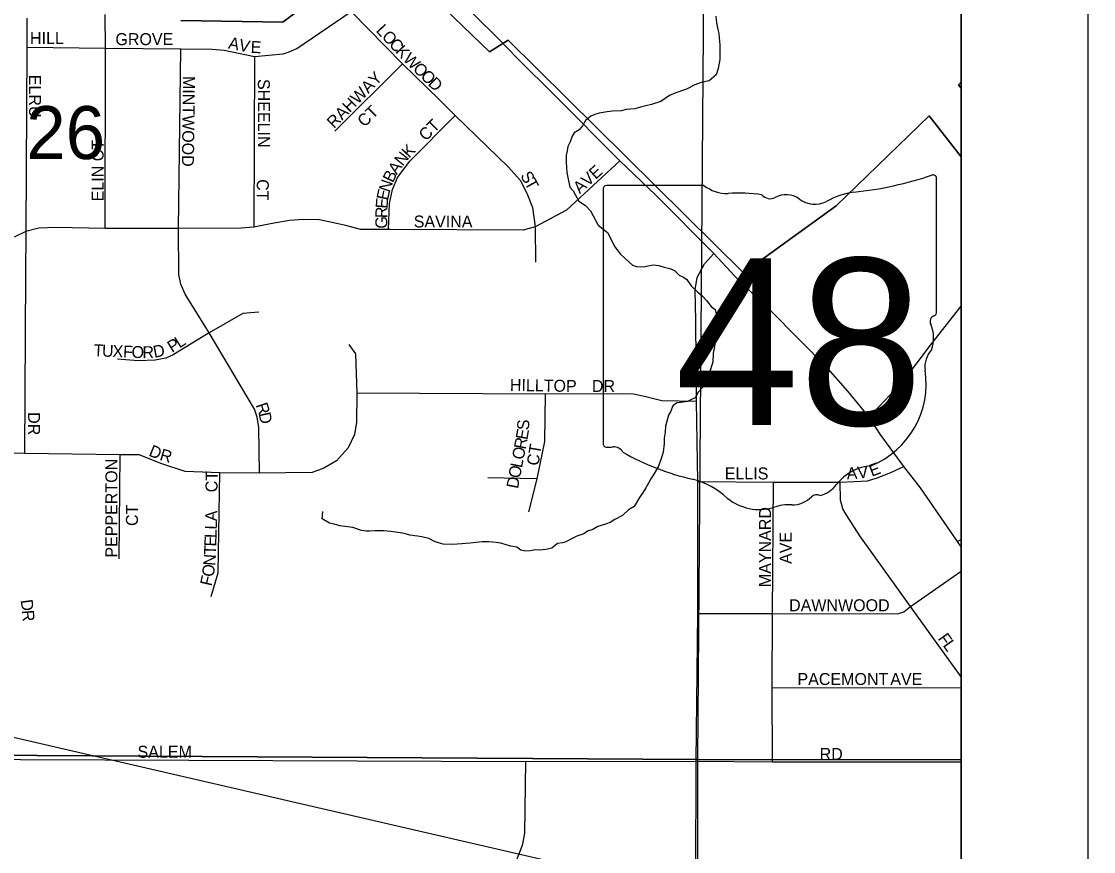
# Model space of a CAD drawing. Extents: x -209 to 4852, y 0 to 905.
# Drawn here: x 375.98 to 392.92, y 256.85 to 269.97 of the extents above; entities that cross this region are included whole.
import ezdxf

# ---------------------------------------------------------------- set-up
doc = ezdxf.new("R2010")
doc.units = 0
for name, color, linetype in [('Default', 7, 'Continuous'), ('GM_X_Airport_Location_Class_2', 7, 'Continuous'), ('GM_X_Airport_Location_Class_3', 7, 'Continuous'), ('GM_X_County_Road', 7, 'Continuous'), ('GM_X_County_Subdivision_Text', 7, 'Continuous'), ('GM_X_Minor_River', 7, 'Continuous'), ('GM_X_Township_Road_Text', 7, 'Continuous'), ('GM_X_Township_ROW', 7, 'Continuous'), ('GM_X_Township_Subdivision', 7, 'Continuous'), ('GM_X_US_Location', 7, 'Continuous'), ('SH_Data', 7, 'Continuous'), ('SH_Text', 7, 'Continuous')]:
    doc.layers.add(name, color=color, linetype=linetype)

msp = doc.modelspace()

# ---------------------------------------------------------------- linework, layer by layer
at = {"layer": 'Default'}
msp.add_lwpolyline([(390.832, 338.559), (254.832, 338.559), (254.832, 202.559), (390.832, 202.559)], close=True, dxfattribs=at)
at = {"layer": 'GM_X_Airport_Location_Class_2'}
msp.add_line((390.775, 261.751), (390.832, 261.784), dxfattribs=at)
for points in [[(376.058, 269.566), (377.306, 269.552), (378.494, 269.542), (378.988, 269.535), (379.179, 269.522), (379.661, 269.42), (380.115, 269.461), (380.21, 269.493), (380.327, 269.548), (381.186, 270.131), (382.291, 270.908)], [(376.058, 270.024), (376.058, 269.566), (376.043, 266.655), (376.039, 265.976)], [(377.3, 266.702), (377.306, 269.552), (377.3, 270.086)], [(381.186, 270.131), (382.001, 269.307), (382.577, 268.74)], [(379.739, 262.835), (379.73, 263.554), (379.704, 263.716), (379.662, 263.844), (378.943, 265.051), (378.566, 265.663), (378.497, 265.819), (378.464, 265.975), (378.457, 266.699), (378.494, 269.542)], [(379.661, 269.42), (379.649, 266.722)], [(380.928, 268.239), (382.001, 269.307)], [(382.577, 268.74), (382.832, 268.489), (383.677, 267.671), (383.86, 267.466), (383.964, 267.26), (384.053, 267.032), (384.099, 266.725), (384.103, 266.17)], [(381.776, 266.685), (381.792, 267.096), (381.842, 267.317), (381.923, 267.507), (382.116, 267.765), (382.832, 268.489)], [(385.433, 267.773), (384.594, 266.991), (384.099, 266.725), (383.907, 266.674), (381.811, 266.685)], [(381.811, 266.685), (381.776, 266.685), (381.337, 266.685), (381.106, 266.749), (380.686, 266.837), (380.436, 266.845), (380.215, 266.829), (379.914, 266.774), (379.649, 266.722), (379.454, 266.705), (378.457, 266.699), (377.3, 266.702), (376.519, 266.719), (376.25, 266.705), (376.043, 266.655), (375.872, 266.572), (375.367, 266.544)], [(386.629, 254.612), (386.643, 258.282), (386.67, 260.614), (386.666, 262.704), (386.649, 263.966), (386.635, 265.244), (386.624, 265.732), (386.657, 265.925), (386.776, 266.144), (386.924, 266.304)], [(376.039, 265.976), (376.024, 263.142)], [(389.377, 263.718), (389.941, 264.321), (390.345, 264.858), (390.832, 265.472)], [(379.727, 265.378), (379.475, 265.358), (378.943, 265.051)], [(378.943, 265.051), (378.373, 264.705), (378.26, 264.652), (378.089, 264.62), (377.822, 264.608), (377.495, 264.638)], [(381.152, 264.869), (381.255, 264.72), (381.279, 264.098), (381.273, 263.64), (381.243, 263.442), (381.143, 263.236), (380.958, 263.03), (380.758, 262.911), (380.57, 262.845), (379.739, 262.835), (379.11, 262.836), (378.564, 262.861), (378.197, 262.981), (377.834, 263.125), (377.535, 263.125), (376.024, 263.142), (375.742, 263.148)], [(386.649, 263.966), (386.097, 263.976), (385.849, 264.038), (385.653, 264.08), (385.481, 264.087), (384.254, 264.082), (381.279, 264.098)], [(384.254, 264.082), (384.247, 263.335), (384.123, 262.743), (383.994, 262.222)], [(377.52, 261.481), (377.535, 263.125)], [(386.666, 262.704), (387.863, 262.692), (388.916, 262.69), (389.349, 262.713), (389.505, 262.757), (389.719, 262.842), (389.924, 262.937)], [(378.974, 260.881), (379.084, 261.26), (379.11, 262.836)], [(384.123, 262.743), (383.348, 262.758)], [(387.847, 258.268), (387.842, 259.441), (387.849, 260.614), (387.863, 262.692)], [(390.832, 259.611), (390.033, 260.724), (389.227, 261.844), (389.011, 262.18), (388.959, 262.269), (388.926, 262.406), (388.916, 262.69)], [(386.67, 260.614), (387.849, 260.614), (389.827, 260.611), (389.927, 260.64), (390.033, 260.724), (390.832, 261.286)], [(387.842, 259.441), (389.423, 259.446), (390.832, 259.442)], [(368.676, 258.342), (375.958, 258.306), (383.945, 258.276), (386.643, 258.282), (387.847, 258.268), (390.832, 258.269)], [(383.945, 258.276), (383.927, 257.141), (383.89, 256.949), (383.736, 256.556), (383.453, 256.136), (383.292, 256.048), (383.133, 256.005), (382.936, 255.998), (382.109, 256.02), (381.995, 255.99), (381.878, 255.916), (381.758, 255.796), (381.698, 255.637), (381.664, 253.92), (381.626, 252.277), (381.644, 252.128), (381.723, 251.754), (381.706, 249.988), (381.716, 249.794), (381.773, 249.483)]]:
    msp.add_lwpolyline(points, dxfattribs=at)
at = {"layer": 'GM_X_County_Road'}
for points in [[(386.951, 270.06), (386.964, 269.954), (386.985, 269.847), (386.999, 269.786), (387.012, 269.656), (387.018, 269.603), (387.014, 269.375), (386.989, 269.231), (386.956, 269.133), (386.848, 269.036), (386.719, 269.008), (386.619, 268.971), (386.489, 268.905), (386.321, 268.848), (386.222, 268.804), (386.083, 268.707), (385.938, 268.664), (385.847, 268.643), (385.763, 268.622), (385.671, 268.593), (385.534, 268.58), (385.458, 268.559), (385.321, 268.554), (385.237, 268.547), (385.108, 268.527), (385.039, 268.505), (384.978, 268.476), (384.893, 268.409), (384.846, 268.326), (384.792, 268.259), (384.715, 268.215), (384.684, 268.162), (384.652, 268.071), (384.612, 267.996), (384.604, 267.928), (384.587, 267.86), (384.585, 267.753), (384.591, 267.662), (384.597, 267.586), (384.611, 267.509), (384.646, 267.357), (384.698, 267.295), (384.786, 267.134), (384.891, 267.064), (384.973, 266.978), (385.091, 266.756), (385.24, 266.639), (385.358, 266.409), (385.447, 266.293), (385.581, 266.169), (385.633, 266.123), (385.701, 266.099), (385.815, 266.097), (385.876, 266.111), (385.967, 266.125), (386.051, 266.116), (386.134, 266.091), (386.224, 266.067), (386.3, 266.035), (386.374, 265.965), (386.442, 265.934), (386.494, 265.895), (386.561, 265.795), (386.665, 265.702), (386.74, 265.632), (386.807, 265.562), (386.881, 265.47), (386.941, 265.423), (386.962, 265.332), (386.969, 265.263), (386.966, 265.103), (386.957, 265.05), (386.94, 264.937), (386.93, 264.83), (386.913, 264.732), (386.903, 264.588), (386.887, 264.527), (386.854, 264.421), (386.838, 264.345), (386.791, 264.278), (386.759, 264.202), (386.674, 264.113), (386.627, 264.022), (386.558, 263.993)], [(386.558, 263.993), (386.504, 263.964), (386.398, 263.95), (386.337, 263.944), (386.275, 263.899), (386.236, 263.801), (386.204, 263.748), (386.156, 263.575), (386.154, 263.483), (386.137, 263.385), (386.135, 263.301), (386.118, 263.165), (386.102, 263.112), (386.085, 263.051), (386.045, 262.945), (385.975, 262.817), (385.928, 262.742), (385.889, 262.675), (385.849, 262.599), (385.802, 262.532), (385.748, 262.449), (385.662, 262.306), (385.57, 262.254), (385.477, 262.165), (385.354, 262.099), (385.285, 262.054), (385.224, 262.033), (385.14, 262.004), (385.086, 261.989), (385.01, 261.945), (384.926, 261.916), (384.864, 261.872), (384.757, 261.836), (384.68, 261.799), (384.581, 261.747), (384.527, 261.733), (384.451, 261.719), (384.359, 261.645), (384.267, 261.624), (384.169, 261.618), (384.1, 261.619), (384.016, 261.605), (383.948, 261.599), (383.872, 261.616), (383.805, 261.662), (383.714, 261.679), (383.654, 261.695), (383.556, 261.728), (383.48, 261.737), (383.366, 261.746), (383.26, 261.748), (383.07, 261.729), (382.94, 261.716), (382.788, 261.703), (382.644, 261.713), (382.569, 261.73), (382.508, 261.754), (382.418, 261.801), (382.305, 261.826), (382.237, 261.835), (382.115, 261.852), (382.063, 261.868), (382.002, 261.884), (381.889, 261.902), (381.813, 261.911), (381.699, 261.92), (381.57, 261.922), (381.479, 261.917), (381.418, 261.918), (381.35, 261.926), (381.214, 261.974), (381.093, 261.992), (381.01, 262.001), (380.919, 262.025), (380.843, 262.042), (380.731, 262.112), (380.741, 262.226)]]:
    msp.add_lwpolyline(points, dxfattribs=at)
at = {"layer": 'GM_X_County_Subdivision_Text'}
for points in [[(383.528, 269.688), (383.521, 269.695), (383.125, 270.086), (383.116, 270.095)], [(390.832, 261.669), (390.775, 261.751), (390.191, 262.6), (389.924, 262.937), (389.553, 263.451), (389.377, 263.718), (389.038, 264.13), (388.728, 264.48), (387.809, 265.417), (387.317, 265.879), (386.924, 266.304), (386.007, 267.229), (385.433, 267.773), (384.418, 268.791), (383.814, 269.396), (383.528, 269.688)]]:
    msp.add_lwpolyline(points, dxfattribs=at)
at = {"layer": 'GM_X_Minor_River'}
for points in [[(366.685, 278.54), (386.82, 278.559), (386.662, 258.306), (366.643, 258.429)], [(390.832, 258.301), (390.832, 278.515), (386.82, 278.559), (386.662, 258.306)], [(386.662, 258.306), (386.645, 238.294), (385.487, 238.317), (366.505, 238.365), (366.643, 258.429)], [(390.832, 238.271), (390.832, 258.301), (386.662, 258.306), (386.645, 238.294)]]:
    msp.add_lwpolyline(points, close=True, dxfattribs=at)
at = {"layer": 'GM_X_Township_Subdivision'}
for p, q in [((390.444, 265.388), (390.444, 267.481)), ((385.17, 267.313), (385.17, 263.311)), ((386.767, 267.382), (385.222, 267.382)), ((390.443, 265.388), (390.444, 265.388))]:
    msp.add_line(p, q, dxfattribs=at)
for centre, radius, start, end in [((388.565, 272.839), 5.592, 275.8445, 288.9065), ((390.385, 267.49), 0.0587, 351.8621, 97.738), ((385.231, 267.322), 0.0611, 98.1301, 188.1301), ((387.134, 267.847), 0.593, 231.6195, 271.1119), ((387.331, 265.135), 2.127, 80.4867, 94.9883), ((387.814, 267.343), 0.171, 219.7921, 297.1024), ((388.065, 266.88), 0.355, 54.4667, 119.1411), ((388.524, 267.514), 0.428, 233.8562, 294.8282), ((389.279, 266.16), 1.125, 97.3462, 120.7689), ((390.43, 265.234), 0.0909, 107.944, 210.337), ((390.381, 265.38), 0.0628, 289.6038, 7.7341), ((389.852, 264.969), 0.545, 340.033, 23.6496), ((390.654, 264.511), 0.397, 136.8065, 186.9296), ((388.879, 264.245), 1.399, 292.3089, 8.9858), ((385.231, 263.302), 0.0616, 171.9584, 258.3066), ((385.241, 263.712), 0.47, 267.339, 280.6039), ((385.337, 263.08), 0.17, 29.7484, 93.2717), ((387.478, 266.676), 4.038, 240.4129, 257.1985), ((389.468, 262.187), 0.766, 94.4031, 142.5768), ((386.274, 261.513), 1.264, 47.1842, 75.836), ((388.498, 262.923), 0.452, 282.8732, 323.2771), ((387.641, 263.06), 0.802, 230.7004, 286.2918), ((388.163, 262.76), 0.427, 268.777, 315.5493), ((388.549, 262.373), 0.12, 65.7517, 132.6484), ((388.104, 261.676), 0.659, 85.6951, 111.2099)]:
    msp.add_arc(centre, radius, start, end, dxfattribs=at)
at = {"layer": 'GM_X_US_Location'}
for points in [[(378.495, 269.99), (380.106, 269.962), (381.675, 271.136), (383.375, 269.495), (383.67, 269.68), (387.393, 265.999), (388.856, 267.062), (390.327, 268.483), (390.832, 267.836), (390.832, 268.918), (390.79, 268.974), (390.832, 269.015), (390.832, 278.706)], [(286.607, 238.38), (390.832, 238.067), (390.832, 267.836), (390.327, 268.483), (388.856, 267.062), (387.393, 265.999), (383.67, 269.68), (383.375, 269.495), (381.675, 271.136), (380.106, 269.962), (378.495, 269.99)], [(286.607, 238.38), (390.832, 238.067), (390.832, 267.836), (390.327, 268.483), (388.856, 267.062), (387.393, 265.999), (383.67, 269.68), (383.375, 269.495), (381.675, 271.136), (380.106, 269.962), (378.495, 269.99)]]:
    msp.add_lwpolyline(points, dxfattribs=at)
msp.add_lwpolyline([(390.832, 269.015), (390.79, 268.974), (390.832, 268.918)], close=True, dxfattribs=at)
msp.add_lwpolyline([(390.832, 269.015), (390.79, 268.974), (390.832, 268.918)], close=True, dxfattribs=at)
at = {"layer": 'SH_Data'}
for p, q in [((392.832, 340.559), (392.832, 200.559)), ((390.832, 338.559), (390.832, 202.559))]:
    msp.add_line(p, q, dxfattribs=at)
at = {"layer": 'SH_Text'}
msp.add_lwpolyline([(329.283, 269.416), (400.488, 252.966), (430.167, 252.966), (430.167, 247.327), (400.495, 247.1)], close=True, dxfattribs=at)

# ---------------------------------------------------------------- texts
at = {"layer": 'GM_X_Airport_Location_Class_3'}
for s, height, rotation, p in [('L', 0.189, 312.9905, (381.57, 269.822)), ('HILL', 0.1894, 0, (376.111, 269.617)), ('GROVE', 0.1894, 0, (377.461, 269.6)), ('A', 0.189, 348.4243, (379.236, 269.549)), ('V', 0.189, 348.4029, (379.4, 269.516)), ('E', 0.189, 357.5296, (379.596, 269.478)), ('O', 0.189, 312.975, (381.661, 269.725)), ('C', 0.189, 312.9887, (381.775, 269.603)), ('K', 0.189, 313.1362, (381.877, 269.493)), ('W', 0.189, 315.2047, (381.996, 269.366)), ('RAHWAY', 0.1894, 45.6582, (380.918, 268.273)), ('O', 0.189, 315.955, (382.152, 269.211)), ('O', 0.189, 315.9427, (382.272, 269.095)), ('ELRU', 0.1894, 270, (376.096, 269.131)), ('MINTWOOD', 0.1894, 269.2724, (378.53, 269.114)), ('SHEELIN', 0.1894, 270, (379.713, 269.065)), ('D', 0.189, 315.9427, (382.392, 268.979)), ('CT', 0.1894, 45, (381.399, 268.293)), ('CT', 0.1894, 45, (382.369, 268.073)), ('ELIN CT', 0.1894, 90, (377.275, 267.131)), ('K', 0.189, 45.9584, (382.103, 267.803)), ('N', 0.189, 51.5825, (382.002, 267.677)), ('B', 0.189, 64.1191, (381.847, 267.414)), ('A', 0.189, 54.9704, (381.909, 267.542)), ('AVE', 0.1894, 42.2752, (384.803, 267.241)), ('CT', 0.1894, 270, (379.696, 267.481)), ('N', 0.189, 71.4268, (381.796, 267.262)), ('S', 0.189, 300.7717, (383.856, 267.537)), ('T', 0.189, 298.8874, (383.923, 267.424)), ('E', 0.189, 78.0579, (381.77, 267.137)), ('E', 0.189, 85.8443, (381.762, 267.011)), ('R', 0.189, 89.3525, (381.76, 266.864)), ('G', 0.189, 89.3661, (381.758, 266.698)), ('SAVINA', 0.1894, 0, (382.177, 266.717)), ('P', 0.189, 31.3463, (378.356, 264.731)), ('L', 0.189, 32.5722, (378.473, 264.803)), ('T', 0.189, 357.4309, (377.112, 264.684)), ('U', 0.189, 357.3984, (377.246, 264.678)), ('X', 0.189, 357.4258, (377.412, 264.67)), ('F', 0.189, 357.4412, (377.579, 264.663)), ('O', 0.189, 358.1463, (377.714, 264.657)), ('R', 0.189, 0.3739, (377.889, 264.651)), ('D', 0.189, 10.741, (378.076, 264.656)), ('HILLTOP', 0.1894, 359.0307, (383.696, 264.134)), ('DR', 0.1894, 0, (384.994, 264.117)), ('R', 0.189, 288.481, (379.677, 263.912)), ('DR', 0.1894, 270, (376.08, 263.798)), ('D', 0.189, 282.2016, (379.723, 263.775)), ('S', 0.189, 87.2642, (383.999, 263.509)), ('R', 0.189, 79.1349, (383.944, 263.201)), ('E', 0.189, 80.1608, (383.973, 263.352)), ('D', 0.189, 337.6912, (377.975, 263.114)), ('R', 0.189, 343.6488, (378.149, 263.044)), ('O', 0.189, 79.1145, (383.913, 263.037)), ('CT', 0.1894, 80.5318, (384.147, 262.942)), ('PEPPERTON', 0.1894, 90, (377.492, 261.498)), ('O', 0.189, 79.1369, (383.856, 262.743)), ('L', 0.189, 79.1454, (383.888, 262.907)), ('ELLIS', 0.1894, 0, (387.094, 262.734)), ('A', 0.189, 3.6309, (389.026, 262.734)), ('V', 0.189, 6.2217, (389.202, 262.745)), ('E', 0.189, 20.7655, (389.418, 262.775)), ('CT', 0.1894, 90, (379.075, 262.531)), ('D', 0.189, 79.1145, (383.825, 262.579)), ('CT', 0.1894, 90, (377.817, 261.998)), ('A', 0.189, 88.1534, (379.068, 262.072)), ('MAYNARD', 0.1894, 90, (387.825, 261.031)), ('L', 0.189, 88.1534, (379.063, 261.939)), ('L', 0.189, 88.1534, (379.059, 261.806)), ('AVE', 0.1894, 90, (388.151, 261.398)), ('T', 0.189, 88.1534, (379.05, 261.539)), ('E', 0.189, 88.1534, (379.055, 261.672)), ('N', 0.189, 85.9721, (379.038, 261.365)), ('O', 0.189, 81.6096, (379.012, 261.185)), ('F', 0.189, 77.2471, (378.98, 261.039)), ('D', 0.189, 277.4964, (375.962, 260.825)), ('DAWNWOOD', 0.1894, 0, (388.111, 260.65)), ('R', 0.189, 274.2534, (375.983, 260.663)), ('F', 0.189, 305.5091, (390.456, 260.219)), ('L', 0.189, 305.5312, (390.534, 260.11)), ('PACEMONT', 0.1894, 0, (388.244, 259.484)), ('AVE', 0.1894, 0, (389.711, 259.484)), ('SALEM', 0.1894, 0, (377.811, 258.334)), ('RD', 0.1894, 0, (388.594, 258.3))]:
    msp.add_text(s, height=height, rotation=rotation, dxfattribs=at).set_placement(p)
at = {"layer": 'GM_X_Township_Road_Text'}
msp.add_text('26', height=0.8371, rotation=0, dxfattribs=at).set_placement((376.052, 267.799))
at = {"layer": 'GM_X_Township_ROW'}
for s in ['s', 'r']:
    msp.add_text(s, height=0.00379, dxfattribs=at).set_placement((387.748, 265.046))
msp.add_text('48', height=0.00379, rotation=0, dxfattribs=at).set_placement((386.794, 264.77))
at = {"layer": 'GM_X_Township_Subdivision'}
msp.add_text('48', height=2.6367, dxfattribs=at).set_placement((386.308, 263.593))

doc.saveas('drawing.dxf')
